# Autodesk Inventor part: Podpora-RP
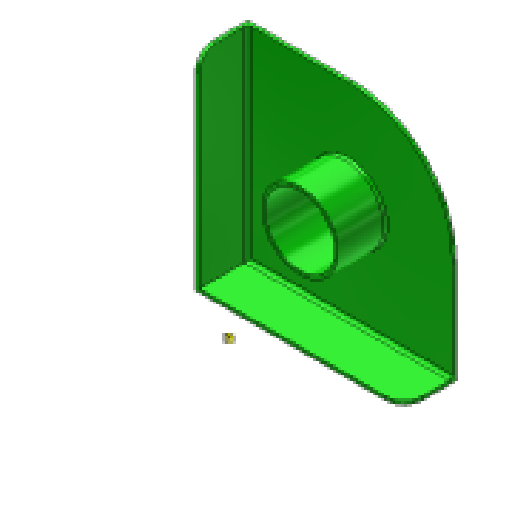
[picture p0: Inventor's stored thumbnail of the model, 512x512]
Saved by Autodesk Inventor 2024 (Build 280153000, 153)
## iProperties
Company: ATC
Shininess: 0.0
Length Units: 11269
Angle Units: 11279
Time Units: 11290
Mass Units: 11283
Length Display Precision: 3
Angle Display Precision: 2
Compacted: True
Created: 2023-03
Part Number: Podpora-RP
Document SubType Name: Modeling
Designer: Andrzej Jaskulski
Material: Stal węglowa
Density: 7.87 g/cm^3
Stock Number: Podpora-RP
Mass: 3651.54 g
Surface Area: 1854.71 cm^2
Volume: 365.154 cm^3
Appearance: Stal
Checked By: A.J.
Engr Approved By: Andrzej Jaskulski
Mfg Approved By: Andrzej Jaskulski
Authority: A.J.
Density: 0.0
Volumn: 0.0
Area: 0.0
PropertySet Name: Model Information
Control State: 0
Master: False
Checked Out: False
Title: A.J.: Kurs R2024-MEP
Author: Andrzej Jaskulski
Revision Number: 1/24
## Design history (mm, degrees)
node "Extrusion1" dims "d1" = 60, "d2" = 0
  sketch "Sketch1"
    geometry: L1 (0, 0)-(240, 0); L2 (240, 0)-(240, 240); L3 (240, 240)-(0, 240); L4 (0, 240)-(0, 0)
    constraints: 8 end point, 2 parallel, 2 perpendicular, 1 horizontal, 1 other
    dimensions: "d0" = 240 distance of L1.start L1.end
node "Hole1" dims "d5" = 80, "d6" = 4, "d7" = 2, "d8" = 60 deg, "d9" = 8, "d10" = 118 deg, "d37" = 6
  sketch "Sketch3"
    geometry: L1 (0, 0)-(240, 0) reference; L2 (0, 240)-(0, 0) reference; 1 further point
    dimensions: "d3" = 120 distance from line of L1 point (120, 120); "d4" = 120 distance from line of L2 point (120, 120)
node "Fillet1" dims "d12" = 20
node "Fillet2" dims "d13" = 120
node "Shell2" dims "d14" = 4
node "Fillet3" dims "d30" = 4
node "Chamfer1" dims "d31" = 4, "d32" = 1, "d35" = 45 deg
node "Bryła1"
node "Korpusy bryłowe"
node "Korpusy powierzchniowe"
node "Szkic6"
node "Szkic7"
